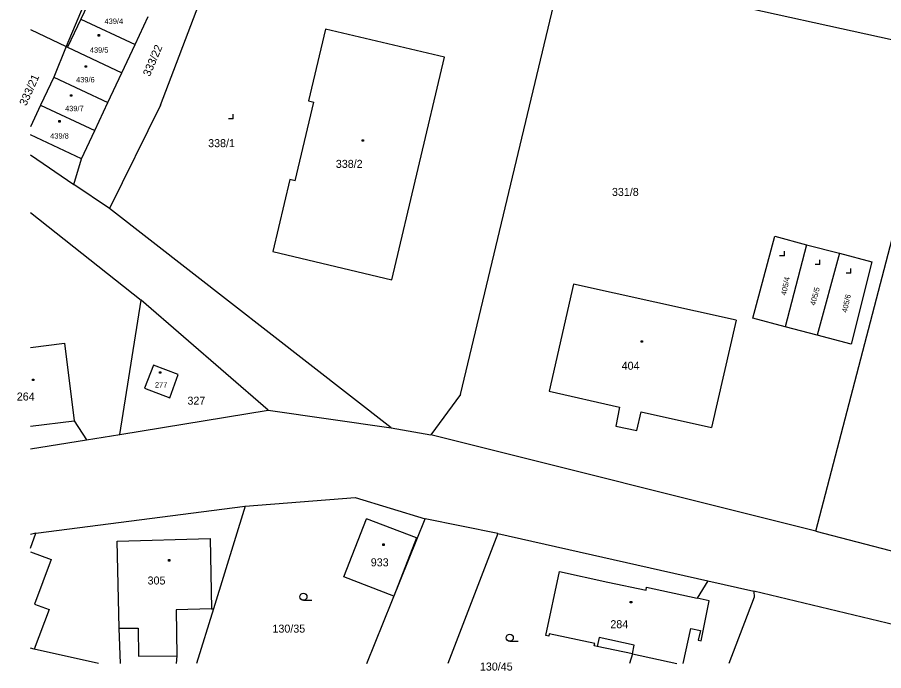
# Model space of a CAD drawing. Extents: x -770973 to -770265, y -1049936 to -1049427.
# Drawn here: x -770957.5 to -770865.5, y -1049935.5 to -1049866.1 of the extents above; entities that cross this region are included whole.
import ezdxf

# ---------------------------------------------------------------- set-up
doc = ezdxf.new("R2010")
doc.units = 0
for name, color, linetype in [('Vrstva 1', 7, 'Continuous'), ('Vrstva 14', 7, 'Continuous'), ('Vrstva 15', 7, 'Continuous'), ('Vrstva 2', 7, 'Continuous'), ('Vrstva 23', 7, 'Continuous'), ('Vrstva 25', 7, 'Continuous')]:
    doc.layers.add(name, color=color, linetype=linetype)

msp = doc.modelspace()

# ---------------------------------------------------------------- linework, layer by layer
at = {"layer": 'Vrstva 1'}
for p, q in [((-770944.6, -1049850.84), (-770952.32, -1049869.22)), ((-770942.3, -1049875.44), (-770935.83, -1049858.36)), ((-770910.45, -1049906.19), (-770899.58, -1049860.79)), ((-770899.58, -1049860.79), (-770859.41, -1049869.62)), ((-770949.36, -1049863.32), (-770950.76, -1049866.31)), ((-770950.76, -1049866.31), (-770952.17, -1049869.3)), ((-770950.76, -1049866.31), (-770945.01, -1049869.01)), ((-770945.01, -1049869.01), (-770943.61, -1049866.02)), ((-770956.13, -1049867.43), (-770952.32, -1049869.22)), ((-770924.78, -1049867.36), (-770926.59, -1049875)), ((-770912.16, -1049870.36), (-770924.78, -1049867.36)), ((-770946.41, -1049872), (-770945.01, -1049869.01)), ((-770952.32, -1049869.22), (-770953.65, -1049872.47)), ((-770952.32, -1049869.22), (-770952.17, -1049869.3)), ((-770952.17, -1049869.3), (-770946.41, -1049872)), ((-770872.73, -1049920.7), (-770859.41, -1049869.62)), ((-770917.76, -1049894), (-770912.16, -1049870.36)), ((-770953.65, -1049872.47), (-770955.06, -1049875.45)), ((-770953.65, -1049872.47), (-770947.9, -1049875.17)), ((-770947.9, -1049875.17), (-770946.41, -1049872)), ((-770955.06, -1049875.45), (-770956.13, -1049877.74)), ((-770955.06, -1049875.45), (-770949.3, -1049878.15)), ((-770949.3, -1049878.15), (-770947.9, -1049875.17)), ((-770942.3, -1049875.44), (-770947.72, -1049886.42)), ((-770928, -1049883.5), (-770926.01, -1049875.14)), ((-770926.59, -1049875), (-770926.01, -1049875.14)), ((-770950.71, -1049881.14), (-770949.3, -1049878.15)), ((-770950.71, -1049881.14), (-770956.13, -1049878.59)), ((-770956.13, -1049880.74), (-770951.52, -1049883.87)), ((-770951.52, -1049883.87), (-770950.71, -1049881.14)), ((-770947.72, -1049886.42), (-770951.52, -1049883.87)), ((-770928.59, -1049883.36), (-770930.38, -1049891)), ((-770928, -1049883.5), (-770928.59, -1049883.36)), ((-770917.8, -1049909.71), (-770947.72, -1049886.42)), ((-770956.13, -1049886.86), (-770944.37, -1049896.17)), ((-770879.4, -1049898.07), (-770877.09, -1049889.36)), ((-770877.09, -1049889.36), (-770873.71, -1049890.28)), ((-770873.71, -1049890.28), (-770875.97, -1049898.99)), ((-770873.71, -1049890.28), (-770870.19, -1049891.18)), ((-770930.38, -1049891), (-770917.76, -1049894)), ((-770870.19, -1049891.18), (-770872.56, -1049899.89)), ((-770870.19, -1049891.18), (-770866.76, -1049892.08)), ((-770866.76, -1049892.08), (-770868.97, -1049900.84)), ((-770898.45, -1049894.45), (-770901.02, -1049905.81)), ((-770881.19, -1049898.28), (-770898.45, -1049894.45)), ((-770946.63, -1049910.42), (-770944.37, -1049896.17)), ((-770930.87, -1049907.85), (-770944.37, -1049896.17)), ((-770881.19, -1049898.28), (-770883.79, -1049909.7)), ((-770875.97, -1049898.99), (-770879.4, -1049898.07)), ((-770872.56, -1049899.89), (-770875.97, -1049898.99)), ((-770868.97, -1049900.84), (-770872.56, -1049899.89)), ((-770943.05, -1049903.05), (-770944, -1049905.51)), ((-770940.43, -1049904.07), (-770943.05, -1049903.05)), ((-770941.33, -1049906.55), (-770940.43, -1049904.07)), ((-770944, -1049905.51), (-770941.33, -1049906.55)), ((-770901.02, -1049905.81), (-770893.58, -1049907.52)), ((-770910.45, -1049906.19), (-770913.59, -1049910.47)), ((-770893.58, -1049907.52), (-770893.96, -1049909.55)), ((-770946.63, -1049910.42), (-770930.87, -1049907.85)), ((-770930.87, -1049907.85), (-770917.8, -1049909.71)), ((-770891.71, -1049910.02), (-770891.26, -1049908.02)), ((-770891.26, -1049908.02), (-770883.79, -1049909.7)), ((-770956.13, -1049909.56), (-770951.48, -1049908.98)), ((-770951.48, -1049908.98), (-770950.16, -1049910.99)), ((-770893.96, -1049909.55), (-770891.71, -1049910.02)), ((-770950.16, -1049910.99), (-770946.63, -1049910.42)), ((-770917.8, -1049909.71), (-770913.59, -1049910.47)), ((-770872.73, -1049920.7), (-770913.59, -1049910.47)), ((-770956.13, -1049911.96), (-770950.16, -1049910.99)), ((-770933.32, -1049918.03), (-770921.64, -1049917.12)), ((-770921.64, -1049917.12), (-770914.21, -1049919.37)), ((-770955.53, -1049920.91), (-770933.32, -1049918.03)), ((-770933.32, -1049918.03), (-770936.69, -1049928.93)), ((-770922.85, -1049925.55), (-770920.42, -1049919.39)), ((-770915.12, -1049921.41), (-770920.42, -1049919.39)), ((-770920.41, -1049934.76), (-770914.21, -1049919.37)), ((-770906.47, -1049920.96), (-770914.21, -1049919.37)), ((-770956.13, -1049922.5), (-770955.53, -1049920.91)), ((-770955.53, -1049920.91), (-770956.13, -1049921.04)), ((-770915.12, -1049921.41), (-770917.54, -1049927.59)), ((-770906.47, -1049920.96), (-770911.78, -1049934.76)), ((-770906.47, -1049920.96), (-770884.18, -1049925.98)), ((-770872.73, -1049920.7), (-770864.02, -1049922.97)), ((-770901.39, -1049931.77), (-770899.93, -1049924.99)), ((-770899.93, -1049924.99), (-770894.81, -1049926.11)), ((-770917.54, -1049927.59), (-770922.85, -1049925.55)), ((-770894.81, -1049926.11), (-770890.75, -1049926.96)), ((-770884.18, -1049925.98), (-770885.33, -1049927.82)), ((-770884.18, -1049925.98), (-770879.31, -1049927.05)), ((-770890.75, -1049926.96), (-770890.69, -1049926.66)), ((-770890.69, -1049926.66), (-770885.33, -1049927.82)), ((-770879.31, -1049927.05), (-770879.28, -1049927.71)), ((-770847.27, -1049934.76), (-770879.31, -1049927.05)), ((-770879.28, -1049927.71), (-770881.96, -1049934.76)), ((-770936.9, -1049928.94), (-770940.65, -1049929.05)), ((-770936.69, -1049928.93), (-770938.49, -1049934.76)), ((-770936.9, -1049928.94), (-770936.69, -1049928.93)), ((-770940.65, -1049929.05), (-770940.59, -1049933.94)), ((-770901.02, -1049931.6), (-770901.07, -1049931.84)), ((-770896.2, -1049932.64), (-770901.02, -1049931.6)), ((-770901.07, -1049931.84), (-770901.39, -1049931.77)), ((-770896.25, -1049932.87), (-770896.2, -1049932.64)), ((-770955.71, -1049933.22), (-770956.13, -1049933.13)), ((-770948.9, -1049934.76), (-770955.71, -1049933.22)), ((-770895.93, -1049932.94), (-770896.25, -1049932.87)), ((-770892.2, -1049933.74), (-770895.93, -1049932.94)), ((-770940.59, -1049933.94), (-770940.63, -1049934.76)), ((-770892.2, -1049933.74), (-770892.52, -1049934.76))]:
    msp.add_line(p, q, dxfattribs=at)
at = {"layer": 'Vrstva 2'}
for p, q in [((-770956.13, -1049901.18), (-770952.5, -1049900.73)), ((-770952.5, -1049900.73), (-770951.48, -1049908.98)), ((-770946.92, -1049921.74), (-770937.05, -1049921.48)), ((-770937.05, -1049921.48), (-770936.9, -1049928.94)), ((-770946.7, -1049931), (-770946.92, -1049921.74)), ((-770956.13, -1049922.89), (-770953.92, -1049923.72)), ((-770953.92, -1049923.72), (-770955.69, -1049928.45)), ((-770884.04, -1049928.1), (-770885.33, -1049927.82)), ((-770955.69, -1049928.45), (-770954.14, -1049929.03)), ((-770884.91, -1049932.34), (-770884.04, -1049928.1)), ((-770954.14, -1049929.03), (-770955.71, -1049933.22)), ((-770946.7, -1049931), (-770944.67, -1049930.99)), ((-770946.56, -1049934.76), (-770946.7, -1049931)), ((-770944.67, -1049930.99), (-770944.64, -1049933.98)), ((-770886.79, -1049934.76), (-770886.01, -1049931.02)), ((-770886.01, -1049931.02), (-770884.98, -1049931.24)), ((-770884.98, -1049931.24), (-770885.2, -1049932.28)), ((-770895.73, -1049932), (-770895.93, -1049932.94)), ((-770892, -1049932.82), (-770895.73, -1049932)), ((-770885.2, -1049932.28), (-770884.91, -1049932.34)), ((-770892.2, -1049933.74), (-770892, -1049932.82)), ((-770944.64, -1049933.98), (-770940.59, -1049933.94)), ((-770892.2, -1049933.74), (-770887.49, -1049934.76))]:
    msp.add_line(p, q, dxfattribs=at)
at = {"layer": 'Vrstva 23'}
for p, q in [((-770934.58, -1049876.9), (-770934.58, -1049876.4)), ((-770934.58, -1049876.9), (-770935.08, -1049876.9)), ((-770876.06, -1049891.44), (-770876.06, -1049890.94)), ((-770876.06, -1049891.44), (-770876.56, -1049891.44)), ((-770872.29, -1049892.37), (-770872.29, -1049891.87)), ((-770872.29, -1049892.37), (-770872.79, -1049892.37)), ((-770868.99, -1049893.3), (-770868.99, -1049892.8)), ((-770868.99, -1049893.3), (-770869.49, -1049893.3)), ((-770927.13, -1049928.04), (-770926.25, -1049928.04)), ((-770905.22, -1049932.39), (-770904.34, -1049932.39))]:
    msp.add_line(p, q, dxfattribs=at)
for centre in [(-770927.13, -1049927.665), (-770905.22, -1049932.015)]:
    msp.add_circle(centre, 0.375, dxfattribs=at)
at = {"layer": 'Vrstva 25'}
for p, q in [((-770948.93, -1049867.96), (-770948.78, -1049867.96)), ((-770948.93, -1049868.11), (-770948.93, -1049867.96)), ((-770948.78, -1049868.11), (-770948.93, -1049868.11)), ((-770948.78, -1049867.96), (-770948.78, -1049868.11)), ((-770950.3, -1049871.26), (-770950.15, -1049871.26)), ((-770950.3, -1049871.41), (-770950.3, -1049871.26)), ((-770950.15, -1049871.41), (-770950.3, -1049871.41)), ((-770950.15, -1049871.26), (-770950.15, -1049871.41)), ((-770951.88, -1049874.36), (-770951.73, -1049874.36)), ((-770951.88, -1049874.51), (-770951.88, -1049874.36)), ((-770951.73, -1049874.51), (-770951.88, -1049874.51)), ((-770951.73, -1049874.36), (-770951.73, -1049874.51)), ((-770953.1, -1049877.09), (-770952.95, -1049877.09)), ((-770953.1, -1049877.24), (-770953.1, -1049877.09)), ((-770952.95, -1049877.24), (-770953.1, -1049877.24)), ((-770952.95, -1049877.09), (-770952.95, -1049877.24)), ((-770920.9, -1049879.14), (-770920.75, -1049879.14)), ((-770920.9, -1049879.29), (-770920.9, -1049879.14)), ((-770920.75, -1049879.29), (-770920.9, -1049879.29)), ((-770920.75, -1049879.14), (-770920.75, -1049879.29)), ((-770891.27, -1049900.48), (-770891.12, -1049900.48)), ((-770891.27, -1049900.63), (-770891.27, -1049900.48)), ((-770891.12, -1049900.63), (-770891.27, -1049900.63)), ((-770891.12, -1049900.48), (-770891.12, -1049900.63)), ((-770942.41, -1049903.77), (-770942.26, -1049903.77)), ((-770942.41, -1049903.92), (-770942.41, -1049903.77)), ((-770942.26, -1049903.92), (-770942.41, -1049903.92)), ((-770942.26, -1049903.77), (-770942.26, -1049903.92)), ((-770955.91, -1049904.54), (-770955.76, -1049904.54)), ((-770955.91, -1049904.69), (-770955.91, -1049904.54)), ((-770955.76, -1049904.69), (-770955.91, -1049904.69)), ((-770955.76, -1049904.54), (-770955.76, -1049904.69)), ((-770918.71, -1049922.05), (-770918.56, -1049922.05)), ((-770918.71, -1049922.2), (-770918.71, -1049922.05)), ((-770918.56, -1049922.2), (-770918.71, -1049922.2)), ((-770918.56, -1049922.05), (-770918.56, -1049922.2)), ((-770941.46, -1049923.72), (-770941.31, -1049923.72)), ((-770941.46, -1049923.87), (-770941.46, -1049923.72)), ((-770941.31, -1049923.87), (-770941.46, -1049923.87)), ((-770941.31, -1049923.72), (-770941.31, -1049923.87)), ((-770892.42, -1049928.15), (-770892.27, -1049928.15)), ((-770892.42, -1049928.3), (-770892.42, -1049928.15)), ((-770892.27, -1049928.3), (-770892.42, -1049928.3)), ((-770892.27, -1049928.15), (-770892.27, -1049928.3))]:
    msp.add_line(p, q, dxfattribs=at)

# ---------------------------------------------------------------- texts
at = {"layer": 'Vrstva 14'}
for s, rotation, p in [('333/22', 66.97971, (-770943.44, -1049872.46)), ('333/21', 66.08601, (-770956.57, -1049875.59))]:
    msp.add_text(s, height=0.85, rotation=rotation, dxfattribs=at).set_placement(p)
for s, p in [('331/8', (-770894.37, -1049885.09)), ('327', (-770939.45, -1049907.26)), ('130/35', (-770930.42, -1049931.47)), ('130/45', (-770908.39, -1049935.5))]:
    msp.add_text(s, height=0.85, dxfattribs=at).set_placement(p)
at = {"layer": 'Vrstva 15'}
for s, height, p in [('439/4', 0.57, (-770948.25, -1049866.82)), ('439/5', 0.57, (-770949.81, -1049869.87)), ('439/6', 0.57, (-770951.27, -1049873.03)), ('439/7', 0.57, (-770952.44, -1049876.09)), ('439/8', 0.57, (-770954.02, -1049879)), ('338/1', 0.85, (-770937.25, -1049879.91)), ('338/2', 0.85, (-770923.69, -1049882.11)), ('404', 0.85, (-770893.34, -1049903.55)), ('277', 0.57, (-770942.9, -1049905.44)), ('264', 0.85, (-770957.57, -1049906.82)), ('933', 0.85, (-770919.98, -1049924.43)), ('305', 0.85, (-770943.68, -1049926.36)), ('284', 0.85, (-770894.54, -1049931))]:
    msp.add_text(s, height=height, dxfattribs=at).set_placement(p)
for s, rotation, p in [('405/4', 78.25554, (-770875.88, -1049895.69)), ('405/5', 75.37914, (-770872.79, -1049896.77)), ('405/6', 77.54562, (-770869.42, -1049897.53))]:
    msp.add_text(s, height=0.57, rotation=rotation, dxfattribs=at).set_placement(p)

doc.saveas('drawing.dxf')
